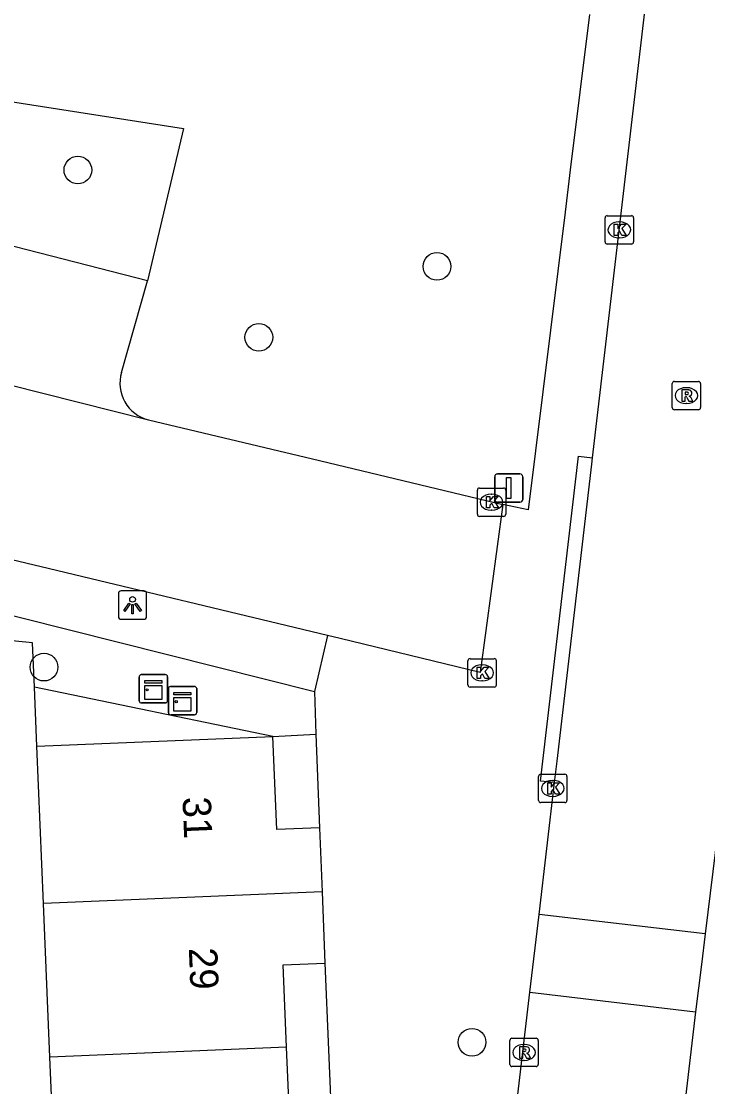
# Model space of a CAD drawing. Extents: x 161243 to 161752, y 384138 to 384885.
# Drawn here: x 161355.25 to 161379.47, y 384281.86 to 384319.46 of the extents above; entities that cross this region are included whole.
import ezdxf

# ---------------------------------------------------------------- set-up
doc = ezdxf.new("R2010")
doc.units = 0
for name, color, linetype in [('IMGEO_Boom', 7, 'Continuous'), ('IMGEO_Groenvoorziening', 7, 'Continuous'), ('IMGEO_Hek', 7, 'Continuous'), ('IMGEO_Kast', 7, 'Continuous'), ('IMGEO_Kolk', 7, 'Continuous'), ('IMGEO_Lichtpunt', 7, 'Continuous'), ('IMGEO_Pand', 7, 'Continuous'), ('IMGEO_Pand_nummerreeks', 7, 'Continuous'), ('IMGEO_Parkeervlak_open', 7, 'Continuous'), ('IMGEO_Rijbaan_lokaal_open', 7, 'Continuous'), ('IMGEO_Rioolput', 7, 'Continuous'), ('IMGEO_Verkeersbordpaal', 7, 'Continuous'), ('IMGEO_Voetpad_open', 7, 'Continuous')]:
    doc.layers.add(name, color=color, linetype=linetype)

msp = doc.modelspace()

# ---------------------------------------------------------------- linework, layer by layer
at = {"layer": 'IMGEO_Boom'}
for centre in [(161357.246, 384314.213), (161369.919, 384310.813), (161363.632, 384308.312), (161356.052, 384296.67), (161371.157, 384283.431)]:
    msp.add_circle(centre, 0.489, dxfattribs=at)
at = {"layer": 'IMGEO_Groenvoorziening'}
for points in [[(161345.806, 384318.051), (161360.974, 384315.683), (161359.706, 384310.307)], [(161364.129, 384294.223), (161355.716, 384295.962), (161355.65, 384297.533), (161341.191, 384298.94), (161339.356, 384291.278)], [(161364.129, 384294.223), (161365.649, 384294.31)]]:
    msp.add_lwpolyline(points, dxfattribs=at)
at = {"layer": 'IMGEO_Hek'}
msp.add_lwpolyline([(161355.803, 384293.876), (161355.716, 384295.962)], dxfattribs=at)
at = {"layer": 'IMGEO_Kast'}
for p, q in [((161359.486, 384296.405), (161360.327, 384296.405)), ((161360.327, 384296.405), (161359.486, 384296.405)), ((161359.411, 384295.48), (161359.411, 384296.321)), ((161359.411, 384296.321), (161359.411, 384295.48)), ((161360.411, 384296.33), (161360.411, 384295.489)), ((161360.411, 384295.489), (161360.411, 384296.33)), ((161360.439, 384295.062), (161360.439, 384295.903)), ((161360.439, 384295.903), (161360.439, 384295.062)), ((161360.514, 384295.987), (161361.355, 384295.987)), ((161361.355, 384295.987), (161360.514, 384295.987)), ((161361.439, 384295.912), (161361.439, 384295.071)), ((161361.439, 384295.071), (161361.439, 384295.912)), ((161360.336, 384295.405), (161359.495, 384295.405)), ((161359.495, 384295.405), (161360.336, 384295.405)), ((161361.364, 384294.987), (161360.523, 384294.987)), ((161360.523, 384294.987), (161361.364, 384294.987))]:
    msp.add_line(p, q, dxfattribs=at)
for points in [[(161359.606, 384296.195), (161360.206, 384296.195), (161360.206, 384296.11), (161359.606, 384296.11), (161359.606, 384296.195)], [(161359.606, 384296.02), (161360.206, 384296.02), (161360.206, 384295.531), (161359.606, 384295.531), (161359.606, 384296.02)], [(161360.634, 384295.777), (161361.234, 384295.777), (161361.234, 384295.692), (161360.634, 384295.692), (161360.634, 384295.777)], [(161360.634, 384295.602), (161361.234, 384295.602), (161361.234, 384295.113), (161360.634, 384295.113), (161360.634, 384295.602)]]:
    msp.add_lwpolyline(points, dxfattribs=at)
for centre in [(161359.69, 384295.869), (161360.718, 384295.451)]:
    msp.add_circle(centre, 0.0377, dxfattribs=at)
for centre, start, end in [((161359.489, 384296.327), 92.4484, 184.2845), ((161359.489, 384296.327), 92.4484, 184.2845), ((161360.333, 384296.327), 2.4484, 94.2845), ((161360.333, 384296.327), 2.4484, 94.2845), ((161360.517, 384295.909), 92.4484, 184.2845), ((161360.517, 384295.909), 92.4484, 184.2845), ((161361.361, 384295.909), 2.4484, 94.2845), ((161361.361, 384295.909), 2.4484, 94.2845), ((161359.489, 384295.483), 182.4484, 274.2845), ((161359.489, 384295.483), 182.4484, 274.2845), ((161360.333, 384295.483), 272.4484, 4.2845), ((161360.333, 384295.483), 272.4484, 4.2845), ((161360.517, 384295.065), 182.4484, 274.2845), ((161360.517, 384295.065), 182.4484, 274.2845), ((161361.361, 384295.065), 272.4484, 4.2845), ((161361.361, 384295.065), 272.4484, 4.2845)]:
    msp.add_arc(centre, 0.0779, start, end, dxfattribs=at)
at = {"layer": 'IMGEO_Kolk'}
for p, q in [((161375.928, 384312.604), (161376.78, 384312.604)), ((161375.853, 384311.678), (161375.853, 384312.53)), ((161376.341, 384312.384), (161376.366, 384312.384)), ((161376.854, 384312.53), (161376.854, 384311.678)), ((161376.364, 384311.824), (161376.339, 384311.824)), ((161376.78, 384311.604), (161375.928, 384311.604)), ((161371.343, 384302.066), (161371.343, 384302.918)), ((161371.418, 384302.992), (161372.27, 384302.992)), ((161371.831, 384302.772), (161371.856, 384302.772)), ((161372.344, 384302.918), (161372.344, 384302.066)), ((161371.854, 384302.212), (161371.829, 384302.212)), ((161372.27, 384301.992), (161371.418, 384301.992)), ((161371.012, 384296.043), (161371.012, 384296.895)), ((161371.087, 384296.969), (161371.939, 384296.969)), ((161372.013, 384296.895), (161372.013, 384296.043)), ((161371.5, 384296.749), (161371.525, 384296.749)), ((161371.523, 384296.189), (161371.498, 384296.189)), ((161371.939, 384295.969), (161371.087, 384295.969)), ((161373.505, 384291.963), (161373.505, 384292.815)), ((161373.58, 384292.889), (161374.432, 384292.889)), ((161373.993, 384292.669), (161374.018, 384292.669)), ((161374.506, 384292.815), (161374.506, 384291.963)), ((161374.432, 384291.889), (161373.58, 384291.889)), ((161374.016, 384292.109), (161373.991, 384292.109))]:
    msp.add_line(p, q, dxfattribs=at)
for points in [[(161375.928, 384312.604), (161376.78, 384312.604)], [(161375.853, 384311.678), (161375.853, 384312.53)], [(161376.174, 384312.304), (161376.297, 384312.304), (161376.297, 384312.153), (161376.427, 384312.304), (161376.591, 384312.304), (161376.445, 384312.153), (161376.598, 384311.904), (161376.446, 384311.904), (161376.361, 384312.068), (161376.297, 384312.001), (161376.297, 384311.904), (161376.174, 384311.904), (161376.174, 384312.304)], [(161376.854, 384312.53), (161376.854, 384311.678)], [(161376.78, 384311.604), (161375.928, 384311.604)], [(161371.343, 384302.066), (161371.343, 384302.918)], [(161371.418, 384302.992), (161372.27, 384302.992)], [(161372.344, 384302.918), (161372.344, 384302.066)], [(161371.664, 384302.692), (161371.787, 384302.692), (161371.787, 384302.541), (161371.917, 384302.692), (161372.081, 384302.692), (161371.935, 384302.541), (161372.088, 384302.292), (161371.936, 384302.292), (161371.851, 384302.456), (161371.787, 384302.389), (161371.787, 384302.292), (161371.664, 384302.292), (161371.664, 384302.692)], [(161372.27, 384301.992), (161371.418, 384301.992)], [(161371.012, 384296.043), (161371.012, 384296.895)], [(161371.087, 384296.969), (161371.939, 384296.969)], [(161372.013, 384296.895), (161372.013, 384296.043)], [(161371.333, 384296.669), (161371.456, 384296.669), (161371.456, 384296.518), (161371.586, 384296.669), (161371.75, 384296.669), (161371.604, 384296.518), (161371.757, 384296.269), (161371.605, 384296.269), (161371.52, 384296.433), (161371.456, 384296.366), (161371.456, 384296.269), (161371.333, 384296.269), (161371.333, 384296.669)], [(161371.939, 384295.969), (161371.087, 384295.969)], [(161373.505, 384291.963), (161373.505, 384292.815)], [(161373.58, 384292.889), (161374.432, 384292.889)], [(161374.506, 384292.815), (161374.506, 384291.963)], [(161373.826, 384292.589), (161373.949, 384292.589), (161373.949, 384292.438), (161374.079, 384292.589), (161374.243, 384292.589), (161374.097, 384292.438), (161374.25, 384292.189), (161374.098, 384292.189), (161374.013, 384292.353), (161373.949, 384292.286), (161373.949, 384292.189), (161373.826, 384292.189), (161373.826, 384292.589)], [(161374.432, 384291.889), (161373.58, 384291.889)]]:
    msp.add_lwpolyline(points, dxfattribs=at)
for centre, start, end in [((161375.93, 384312.528), 91.552, 178.448), ((161375.93, 384312.528), 91.552, 178.448), ((161376.778, 384312.528), 1.552, 88.448), ((161376.778, 384312.528), 1.552, 88.448), ((161375.93, 384311.68), 181.552, 268.448), ((161375.93, 384311.68), 181.552, 268.448), ((161376.778, 384311.68), 271.552, 358.448), ((161376.778, 384311.68), 271.552, 358.448), ((161371.42, 384302.916), 91.552, 178.448), ((161371.42, 384302.916), 91.552, 178.448), ((161372.268, 384302.916), 1.552, 88.448), ((161372.268, 384302.916), 1.552, 88.448), ((161371.42, 384302.068), 181.552, 268.448), ((161371.42, 384302.068), 181.552, 268.448), ((161372.268, 384302.068), 271.552, 358.448), ((161372.268, 384302.068), 271.552, 358.448), ((161371.089, 384296.893), 91.552, 178.448), ((161371.089, 384296.893), 91.552, 178.448), ((161371.937, 384296.893), 1.552, 88.448), ((161371.937, 384296.893), 1.552, 88.448), ((161371.089, 384296.045), 181.552, 268.448), ((161371.089, 384296.045), 181.552, 268.448), ((161371.937, 384296.045), 271.552, 358.448), ((161371.937, 384296.045), 271.552, 358.448), ((161373.582, 384292.813), 91.552, 178.448), ((161373.582, 384292.813), 91.552, 178.448), ((161374.43, 384292.813), 1.552, 88.448), ((161374.43, 384292.813), 1.552, 88.448), ((161373.582, 384291.965), 181.552, 268.448), ((161373.582, 384291.965), 181.552, 268.448), ((161374.43, 384291.965), 271.552, 358.448), ((161374.43, 384291.965), 271.552, 358.448)]:
    msp.add_arc(centre, 0.0765, start, end, dxfattribs=at)
for centre, major_axis, ratio, start_param, end_param in [((161376.34, 384312.104), (-0.387, 0.002), 0.722429, 4.712389, 7.853982), ((161376.365, 384312.104), (-0.39, 0.002), 0.717154, 1.570796, 4.712389), ((161371.83, 384302.492), (-0.387, 0.002), 0.722429, 4.712389, 7.853982), ((161371.855, 384302.492), (-0.39, 0.002), 0.717154, 1.570796, 4.712389), ((161371.499, 384296.469), (-0.387, 0.002), 0.722429, 4.712389, 7.853982), ((161371.524, 384296.469), (-0.39, 0.002), 0.717154, 1.570796, 4.712389), ((161373.992, 384292.389), (-0.387, 0.002), 0.722429, 4.712389, 7.853982), ((161374.017, 384292.389), (-0.39, 0.002), 0.717154, 1.570796, 4.712389)]:
    msp.add_ellipse(centre, major_axis=major_axis, ratio=ratio, start_param=start_param, end_param=end_param, dxfattribs=at)
at = {"layer": 'IMGEO_Lichtpunt'}
for p, q in [((161358.676, 384299.263), (161358.676, 384298.456)), ((161358.676, 384299.263), (161358.676, 384298.456)), ((161359.578, 384299.358), (161358.77, 384299.358)), ((161359.578, 384299.358), (161358.77, 384299.358)), ((161359.672, 384298.456), (161359.672, 384299.263)), ((161359.672, 384298.456), (161359.672, 384299.263)), ((161358.77, 384298.362), (161359.578, 384298.362)), ((161358.77, 384298.362), (161359.578, 384298.362))]:
    msp.add_line(p, q, dxfattribs=at)
for points in [[(161359.05, 384298.927), (161359.089, 384298.899), (161358.901, 384298.637), (161358.863, 384298.664), (161359.05, 384298.927)], [(161359.152, 384298.879), (161359.199, 384298.879), (161359.199, 384298.557), (161359.152, 384298.557), (161359.152, 384298.879)], [(161359.262, 384298.899), (161359.3, 384298.926), (161359.487, 384298.664), (161359.448, 384298.636), (161359.262, 384298.899)]]:
    msp.add_lwpolyline(points, dxfattribs=at)
msp.add_circle((161359.175, 384299.061), 0.0994, dxfattribs=at)
for centre, start, end in [((161358.77, 384299.263), 90, 180), ((161358.77, 384299.263), 90, 180), ((161359.578, 384299.263), 0, 90), ((161359.578, 384299.263), 0, 90), ((161358.77, 384298.456), 180, 270), ((161358.77, 384298.456), 180, 270), ((161359.578, 384298.456), 270, 0), ((161359.578, 384298.456), 270, 360)]:
    msp.add_arc(centre, 0.0946, start, end, dxfattribs=at)
at = {"layer": 'IMGEO_Pand'}
for points in [[(161356.035, 384288.333), (161355.803, 384293.876), (161364.129, 384294.223)], [(161365.768, 384291), (161364.266, 384290.938), (161364.129, 384294.223)], [(161365.768, 384291), (161365.862, 384288.743)], [(161365.862, 384288.743), (161356.035, 384288.333)], [(161365.862, 384288.743), (161365.967, 384286.221)], [(161356.262, 384282.909), (161356.035, 384288.333)], [(161364.613, 384283.257), (161364.492, 384286.16), (161365.967, 384286.221)], [(161364.613, 384283.257), (161356.262, 384282.909)], [(161366.223, 384280.106), (161364.747, 384280.045), (161364.613, 384283.257)], [(161356.488, 384277.486), (161356.262, 384282.909)]]:
    msp.add_lwpolyline(points, dxfattribs=at)
at = {"layer": 'IMGEO_Parkeervlak_open'}
for points in [[(161359.706, 384310.307), (161343.987, 384314.34), (161342.197, 384314.772)], [(161358.781, 384307.069), (161359.706, 384310.307)]]:
    msp.add_lwpolyline(points, dxfattribs=at)
msp.add_arc((161360.076, 384306.698), 1.347, 164.0327, 255.3759, dxfattribs=at)
at = {"layer": 'IMGEO_Rijbaan_lokaal_open'}
for points in [[(161375.412, 384304.063), (161380.553, 384347.92), (161380.816, 384350.22)], [(161340.013, 384310.37), (161359.736, 384305.395)], [(161359.736, 384305.395), (161365.529, 384304.017), (161372.24, 384302.407)], [(161374.069, 384292.593), (161374.158, 384293.356), (161375.385, 384303.831), (161375.412, 384304.063)], [(161366.059, 384297.781), (161355.95, 384300.205), (161351.506, 384301.273), (161347.56, 384302.264), (161344.034, 384303.169)], [(161372.24, 384302.407), (161371.443, 384296.485), (161366.499, 384297.676), (161366.059, 384297.781)], [(161380.767, 384298.362), (161380.712, 384297.896), (161380.279, 384294.53), (161379.384, 384287.252)], [(161373.523, 384287.939), (161374.069, 384292.593)], [(161373.201, 384285.193), (161373.523, 384287.939)], [(161379.384, 384287.252), (161373.523, 384287.939)], [(161379.384, 384287.252), (161379.251, 384286.174), (161379.046, 384284.508)], [(161372.354, 384277.971), (161373.201, 384285.193)], [(161373.201, 384285.193), (161379.046, 384284.508)], [(161379.046, 384284.508), (161378.196, 384277.255), (161377.986, 384275.243), (161377.967, 384274.752), (161377.968, 384274.518), (161377.976, 384274.251)]]:
    msp.add_lwpolyline(points, dxfattribs=at)
at = {"layer": 'IMGEO_Rioolput'}
for p, q in [((161378.221, 384305.828), (161378.221, 384306.68)), ((161378.296, 384306.754), (161379.148, 384306.754)), ((161378.709, 384306.534), (161378.734, 384306.534)), ((161379.222, 384306.68), (161379.222, 384305.828)), ((161378.732, 384305.974), (161378.707, 384305.974)), ((161379.148, 384305.754), (161378.296, 384305.754)), ((161372.49, 384282.646), (161372.49, 384283.498)), ((161372.565, 384283.572), (161373.417, 384283.572)), ((161372.978, 384283.352), (161373.003, 384283.352)), ((161373.491, 384283.498), (161373.491, 384282.646)), ((161373.417, 384282.572), (161372.565, 384282.572)), ((161373.001, 384282.792), (161372.976, 384282.792))]:
    msp.add_line(p, q, dxfattribs=at)
for points in [[(161378.221, 384305.828), (161378.221, 384306.68)], [(161378.296, 384306.754), (161379.148, 384306.754)], [(161379.222, 384306.68), (161379.222, 384305.828)], [(161378.81, 384306.452), (161378.558, 384306.454), (161378.558, 384306.054)], [(161378.558, 384306.054), (161378.682, 384306.054), (161378.682, 384306.216), (161378.693, 384306.216)], [(161378.736, 384306.373), (161378.682, 384306.373), (161378.682, 384306.292)], [(161378.682, 384306.292), (161378.734, 384306.292)], [(161378.74, 384306.187), (161378.811, 384306.054), (161378.951, 384306.054), (161378.886, 384306.18)], [(161379.148, 384305.754), (161378.296, 384305.754)], [(161372.49, 384282.646), (161372.49, 384283.498)], [(161372.565, 384283.572), (161373.417, 384283.572)], [(161373.079, 384283.27), (161372.827, 384283.272), (161372.827, 384282.872)], [(161373.491, 384283.498), (161373.491, 384282.646)], [(161372.827, 384282.872), (161372.951, 384282.872), (161372.951, 384283.034), (161372.962, 384283.034)], [(161373.005, 384283.191), (161372.951, 384283.191), (161372.951, 384283.11)], [(161372.951, 384283.11), (161373.003, 384283.11)], [(161373.009, 384283.005), (161373.08, 384282.872), (161373.22, 384282.872), (161373.155, 384282.998)], [(161373.417, 384282.572), (161372.565, 384282.572)]]:
    msp.add_lwpolyline(points, dxfattribs=at)
for centre, radius, start, end in [((161378.298, 384306.678), 0.0765, 91.552, 178.448), ((161378.298, 384306.678), 0.0765, 91.552, 178.448), ((161379.146, 384306.678), 0.0765, 1.552, 88.448), ((161379.146, 384306.678), 0.0765, 1.552, 88.448), ((161378.692, 384306.163), 0.0533, 26.0293, 88.6989), ((161378.718, 384306.481), 0.19, 274.7715, 282.9687), ((161378.742, 384306.277), 0.0964, 77.0061, 93.1865), ((161378.756, 384306.334), 0.0378, 276.6634, 79.6772), ((161378.809, 384306.342), 0.109, 350.3612, 89.416), ((161378.807, 384306.342), 0.112, 277.5842, 350.9817), ((161378.791, 384306.127), 0.108, 29.5134, 73.7905), ((161378.298, 384305.83), 0.0765, 181.552, 268.448), ((161378.298, 384305.83), 0.0765, 181.552, 268.448), ((161379.146, 384305.83), 0.0765, 271.552, 358.448), ((161379.146, 384305.83), 0.0765, 271.552, 358.448), ((161372.567, 384283.496), 0.0765, 91.552, 178.448), ((161372.567, 384283.496), 0.0765, 91.552, 178.448), ((161373.078, 384283.16), 0.109, 350.3612, 89.416), ((161373.415, 384283.496), 0.0765, 1.552, 88.448), ((161373.415, 384283.496), 0.0765, 1.552, 88.448), ((161372.961, 384282.981), 0.0533, 26.0293, 88.6989), ((161372.987, 384283.299), 0.19, 274.7715, 282.9687), ((161373.011, 384283.095), 0.0964, 77.0061, 93.1865), ((161373.025, 384283.152), 0.0378, 276.6634, 79.6772), ((161373.076, 384283.16), 0.112, 277.5842, 350.9817), ((161373.06, 384282.945), 0.108, 29.5134, 73.7905), ((161372.567, 384282.648), 0.0765, 181.552, 268.448), ((161372.567, 384282.648), 0.0765, 181.552, 268.448), ((161373.415, 384282.648), 0.0765, 271.552, 358.448), ((161373.415, 384282.648), 0.0765, 271.552, 358.448)]:
    msp.add_arc(centre, radius, start, end, dxfattribs=at)
for centre, major_axis, ratio, start_param, end_param in [((161378.708, 384306.254), (-0.387, 0.002), 0.722429, 4.712389, 7.853982), ((161378.733, 384306.254), (-0.39, 0.002), 0.717154, 1.570796, 4.712389), ((161372.977, 384283.072), (-0.387, 0.002), 0.722429, 4.712389, 7.853982), ((161373.002, 384283.072), (-0.39, 0.002), 0.717154, 1.570796, 4.712389)]:
    msp.add_ellipse(centre, major_axis=major_axis, ratio=ratio, start_param=start_param, end_param=end_param, dxfattribs=at)
at = {"layer": 'IMGEO_Verkeersbordpaal'}
for p, q in [((161371.957, 384302.592), (161371.957, 384303.392)), ((161371.957, 384303.392), (161371.957, 384302.592)), ((161372.057, 384303.492), (161372.847, 384303.492)), ((161372.847, 384303.492), (161372.057, 384303.492)), ((161372.947, 384303.392), (161372.947, 384302.592)), ((161372.947, 384302.592), (161372.947, 384303.392)), ((161372.847, 384302.492), (161372.057, 384302.492)), ((161372.057, 384302.492), (161372.847, 384302.492))]:
    msp.add_line(p, q, dxfattribs=at)
msp.add_lwpolyline([(161372.377, 384303.367), (161372.527, 384303.367), (161372.527, 384302.617), (161372.377, 384302.617), (161372.377, 384303.367)], dxfattribs=at)
for centre, start, end in [((161372.057, 384303.392), 90, 180), ((161372.057, 384303.392), 90, 180), ((161372.847, 384303.392), 0, 90), ((161372.847, 384303.392), 360, 90), ((161372.057, 384302.592), 180, 270), ((161372.057, 384302.592), 180, 270), ((161372.847, 384302.592), 270, 0), ((161372.847, 384302.592), 270, 0)]:
    msp.add_arc(centre, 0.1, start, end, dxfattribs=at)
at = {"layer": 'IMGEO_Voetpad_open'}
for points in [[(161375.299, 384319.702), (161374.623, 384314.221), (161374.439, 384312.732), (161373.142, 384302.222), (161372.24, 384302.407)], [(161374.069, 384292.593), (161373.573, 384292.651), (161374.916, 384304.121), (161375.412, 384304.063)], [(161343.158, 384301.452), (161365.595, 384295.806)], [(161366.059, 384297.781), (161365.595, 384295.806)], [(161365.595, 384295.806), (161365.649, 384294.31)], [(161365.649, 384294.31), (161365.768, 384291)], [(161365.967, 384286.221), (161366.223, 384280.106)]]:
    msp.add_lwpolyline(points, dxfattribs=at)

# ---------------------------------------------------------------- texts
at = {"layer": 'IMGEO_Pand_nummerreeks'}
for s, p in [('31', (161360.937, 384292.079)), ('29', (161361.16, 384286.754))]:
    msp.add_text(s, height=1, rotation=272.4061, dxfattribs=at).set_placement(p)

doc.saveas('drawing.dxf')
